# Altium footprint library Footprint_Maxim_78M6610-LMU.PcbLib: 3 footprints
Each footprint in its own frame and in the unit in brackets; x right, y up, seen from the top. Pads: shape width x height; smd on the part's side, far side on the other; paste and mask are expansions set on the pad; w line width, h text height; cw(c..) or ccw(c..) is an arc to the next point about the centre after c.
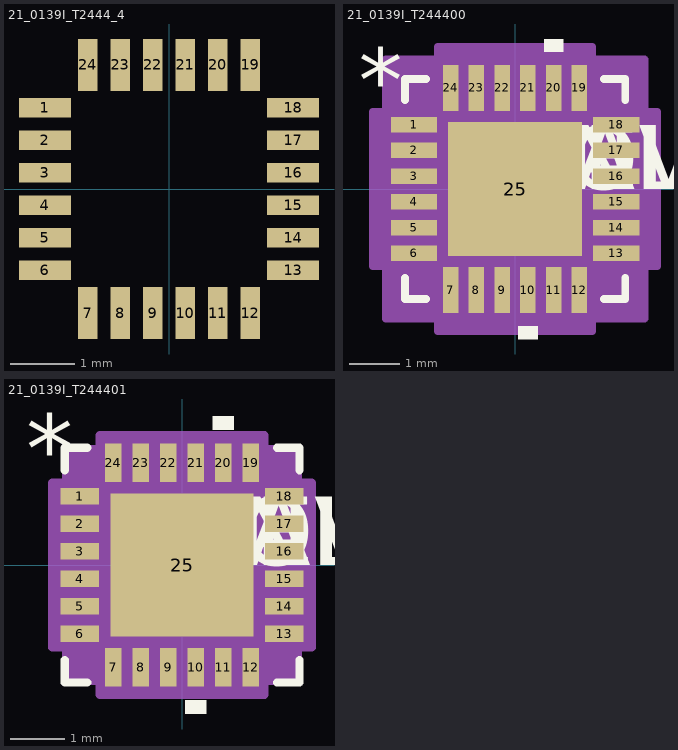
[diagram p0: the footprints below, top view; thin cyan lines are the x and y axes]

## 21_0139I_T2444_4 [mil]
pads (24):
  rect 32x12 smd: 1(-76.5,50) 2(-76.5,30) 3(-76.5,10) 4(-76.5,-10) 5(-76.5,-30) 6(-76.5,-50) 13(76.5,-50) 14(76.5,-30) 15(76.5,-10) 16(76.5,10) 17(76.5,30) 18(76.5,50)
  rect 12x32 smd: 7(-50,-76.5) 8(-30,-76.5) 9(-10,-76.5) 10(10,-76.5) 11(30,-76.5) 12(50,-76.5) 19(50,76.5) 20(30,76.5) 21(10,76.5) 22(-10,76.5) 23(-30,76.5) 24(-50,76.5)

## 21_0139I_T244400 [mil]
pads (25):
  rect 36x12 smd: 1(-78.5,50) 2(-78.5,30) 3(-78.5,10) 4(-78.5,-10) 5(-78.5,-30) 6(-78.5,-50) 13(78.5,-50) 14(78.5,-30) 15(78.5,-10) 16(78.5,10) 17(78.5,30) 18(78.5,50)
  rect 12x36 smd: 7(-50,-78.5) 8(-30,-78.5) 9(-10,-78.5) 10(10,-78.5) 11(30,-78.5) 12(50,-78.5) 19(50,78.5) 20(30,78.5) 21(10,78.5) 22(-10,78.5) 23(-30,78.5) 24(-50,78.5)
  rect 104x104 smd paste-51.5: 25(0,0)
Top Overlay:
  region: 17.5,-106.5 2.5,-106.5 2.5,-116.5 17.5,-116.5
  region: 37.5,106.5 22.5,106.5 22.5,116.5 37.5,116.5
  lines w6: -85.5,-69.1 -85.5,-85.5 -69.1,-85.5 ; -85.5,69.1 -85.5,85.5 -69.1,85.5 ; 69.1,-85.5 85.5,-85.5 85.5,-69.1 ; 69.1,85.5 85.5,85.5 85.5,69.1
  text "*" at -121.5,60 h50
  text "PN" at 0,0 h50
  text "DEV" at 0,0 h50
  text "VAL" at 0,0 h50
  text "TOL" at 0,0 h50
Top Paste:
  region: -3.94,48.06 -48.06,48.06 -48.06,3.94 -3.94,3.94
  region: -3.94,-3.94 -48.06,-3.94 -48.06,-48.06 -3.94,-48.06
  region: 48.06,48.06 3.94,48.06 3.94,3.94 48.06,3.94
  region: 48.06,-3.94 3.94,-3.94 3.94,-48.06 48.06,-48.06
Mechanical 13:
  text "*" at -60.5,60 h50
  text "RefDes2" at 0,0 h50
Mechanical 15:
  region: -60,-100.5 -100.5,-100.5 -100.5,-60 -110.5,-60 -110.5,60 -100.5,60 -100.5,100.5 -60,100.5 -60,110.5 60,110.5 60,100.5 100.5,100.5 100.5,60 110.5,60 110.5,-60 100.5,-60 100.5,-100.5 60,-100.5 60,-110.5 -60,-110.5
  lines w6: -110.5,-60 -100.5,-60 -100.5,-100.5 -60,-100.5 -60,-110.5 60,-110.5 60,-100.5 100.5,-100.5 100.5,-60 110.5,-60 110.5,60 100.5,60 100.5,100.5 60,100.5 60,110.5 -60,110.5 -60,100.5 -100.5,100.5 -100.5,60 -110.5,60 -110.5,-60

## 21_0139I_T244401 [mil]
pads (25):
  rect 28x12 smd: 1(-74.5,50) 2(-74.5,30) 3(-74.5,10) 4(-74.5,-10) 5(-74.5,-30) 6(-74.5,-50) 13(74.5,-50) 14(74.5,-30) 15(74.5,-10) 16(74.5,10) 17(74.5,30) 18(74.5,50)
  rect 12x28 smd: 7(-50,-74.5) 8(-30,-74.5) 9(-10,-74.5) 10(10,-74.5) 11(30,-74.5) 12(50,-74.5) 19(50,74.5) 20(30,74.5) 21(10,74.5) 22(-10,74.5) 23(-30,74.5) 24(-50,74.5)
  rect 104x104 smd paste-51.5: 25(0,0)
Top Overlay:
  region: 17.5,-98.5 2.5,-98.5 2.5,-108.5 17.5,-108.5
  region: 37.5,98.5 22.5,98.5 22.5,108.5 37.5,108.5
  lines w6: -85.5,-69.1 -85.5,-85.5 -69.1,-85.5 ; -85.5,69.1 -85.5,85.5 -69.1,85.5 ; 69.1,-85.5 85.5,-85.5 85.5,-69.1 ; 69.1,85.5 85.5,85.5 85.5,69.1
  text "*" at -113.5,60 h50
  text "PN" at 0,0 h50
  text "DEV" at 0,0 h50
  text "VAL" at 0,0 h50
  text "TOL" at 0,0 h50
Top Paste:
  region: -3.94,48.06 -48.06,48.06 -48.06,3.94 -3.94,3.94
  region: -3.94,-3.94 -48.06,-3.94 -48.06,-48.06 -3.94,-48.06
  region: 48.06,48.06 3.94,48.06 3.94,3.94 48.06,3.94
  region: 48.06,-3.94 3.94,-3.94 3.94,-48.06 48.06,-48.06
Mechanical 13:
  text "*" at -60.5,60 h50
  text "RefDes2" at 0,0 h50
Mechanical 15:
  region: -60,-84.5 -84.5,-84.5 -84.5,-60 -94.5,-60 -94.5,60 -84.5,60 -84.5,84.5 -60,84.5 -60,94.5 60,94.5 60,84.5 84.5,84.5 84.5,60 94.5,60 94.5,-60 84.5,-60 84.5,-84.5 60,-84.5 60,-94.5 -60,-94.5
  lines w6: -94.5,-60 -84.5,-60 -84.5,-84.5 -60,-84.5 -60,-94.5 60,-94.5 60,-84.5 84.5,-84.5 84.5,-60 94.5,-60 94.5,60 84.5,60 84.5,84.5 60,84.5 60,94.5 -60,94.5 -60,84.5 -84.5,84.5 -84.5,60 -94.5,60 -94.5,-60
